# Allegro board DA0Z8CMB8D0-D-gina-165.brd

Outline 251.48 x 174.46 mm; copper layers: TOP, SGND, IN1, IN2, SVCC, IN3, SGND1, BOTTOM. Coordinates in mm from the lower left corner of the outline.

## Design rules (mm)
constraint set DEFAULT: min track width 0.14
net group DFP-S5(4: nets CRT_AUXN_C CRT_AUXP_C
net group DFP-S5(4.5: nets VMA_CLK0 VMA_CLK0#
net group W5(5.25)-T13B: nets VGA_COMP VGA_RST
net group W99-T123B: nets N103095748 TERM0
net group DFP-S4(4: nets M_A_DQS1 M_A_DQS2 M_A_DQS3 M_A_DQS5 M_A_DQS#1 M_A_DQS#2 M_A_DQS#3 M_A_DQS#5
net group DFP-S5(4: nets CRT_TXN0_C CRT_TXN1_C CRT_TXP0_C CRT_TXP1_C EDP_AUXN EDP_AUXP EDP_TXN0 EDP_TXN0_C EDP_TXN1 EDP_TXN1_C EDP_TXN2 EDP_TXN2_C EDP_TXN3 EDP_TXN3_C EDP_TXP0 EDP_TXP0_C EDP_TXP1 EDP_TXP1_C EDP_TXP2 EDP_TXP2_C EDP_TXP3 EDP_TXP3_C INT_HDMICLK+ INT_HDMICLK- INT_HDMITX0N INT_HDMITX0P PCIE_RXN3_C PCIE_RXP3_C PCIE_TX3+ PCIE_TX3- PCIE_TX4+ PCIE_TX4- PEG_RX0 PEG_RX#0 R_PEG_TX0 R_PEG_TX1 R_PEG_TX2 R_PEG_TX#0 R_PEG_TX#1 R_PEG_TX#2 USB3_TXN0 USB3_TXN0_C USB3_TXN1 USB3_TXN1_C USB3_TXP0 USB3_TXP0_C USB3_TXP1 USB3_TXP1_C USBP0+_C USBP0-_C USBP1+_R USBP1-_R USBP5+ USBP5+_R USBP5- USBP5-_R USBP6+ USBP6+_R USBP6- USBP6-_R WIGIG_TX3+ WIGIG_TX3-
net group DFP-S7(5.5: nets CK_XDP_N_R CK_XDP_P_R CLK_PCIE_WIGIGN CLK_PCIE_WIGIGP CLK_PCIE_XDPN CLK_PCIE_XDPP
net group DFP-S12(10: nets TX0N_R TX0P_R TX1N_R TX1P_R TX2N_R TX2P_R TX3N_R TX3P_R X-TX2N X-TX2P X-TX3N X-TX3P
net group W5(4.5: nets CRT_B1 CRT_BLU CRT_G1 CRT_GRE CRT_HPD CRT_R1 CRT_RED CRTHSYNC CRTVSYNC HSYNC ISPSCL ISPSDA VSYNC
net group W5-T13B: nets ACZ_SDIN0_R HDA_BCLK_R HDA_RST#_R HDA_SDO_R HDA_SYNC_R PCH_AZ_CODEC_BITCLK PCH_AZ_CODEC_RST# PCH_AZ_CODEC_SDIN0 PCH_AZ_CODEC_SDOUT PCH_AZ_CODEC_SYNC
net group W5.5(3.5)-T3B: nets SD_CLK
net group W5.5(4.5: nets M_B_DQ0 M_B_DQ1 M_B_DQ2 M_B_DQ3 M_B_DQ4 M_B_DQ5 M_B_DQ6 M_B_DQ7 M_B_DQ8 M_B_DQ9 M_B_DQ10 M_B_DQ11 M_B_DQ12 M_B_DQ13 M_B_DQ14 M_B_DQ15 M_B_DQ16 M_B_DQ17 M_B_DQ18 M_B_DQ19 M_B_DQ20 M_B_DQ21 M_B_DQ22 M_B_DQ23 M_B_DQ24 M_B_DQ25 M_B_DQ26 M_B_DQ27 M_B_DQ28 M_B_DQ29 M_B_DQ30 M_B_DQ31 M_B_DQ32 M_B_DQ33 M_B_DQ34 M_B_DQ35 M_B_DQ36 M_B_DQ37 M_B_DQ38 M_B_DQ39 M_B_DQ40 M_B_DQ41 M_B_DQ42 M_B_DQ43 M_B_DQ44 M_B_DQ45 M_B_DQ46 M_B_DQ47 M_B_DQ48 M_B_DQ49 M_B_DQ50 M_B_DQ51 M_B_DQ52 M_B_DQ53 M_B_DQ54 M_B_DQ55 M_B_DQ56 M_B_DQ57 M_B_DQ58 M_B_DQ59 M_B_DQ60 M_B_DQ61 M_B_DQ62 M_B_DQ63
net group W5.5(4.5: nets 27M_XTAL_IN_R 27M_XTAL_OUT A_LAD0_R A_LAD2_R A_LAD3_R CATERR# CLK_PCH_PCI3 CLK_PCH_PCI4 CLK_PCI_EC CLK_PCI_LPC CPU_DRAMRST# DDR_PG_CTRL H_PROCHOT# H_PROCHOT#_R HDMI_DDCCLK_COM HDMI_DDCCLK_MB HDMI_DDCCLK_SW HDMI_DDCDATA_COM HDMI_DDCDATA_MB HDMI_DDCDATA_SW LAN_XTAL2 LAN_XTALI LPC_LAD0 LPC_LAD1 LPC_LAD2 LPC_LAD3 LPC_LFRAME# PCH_SPI_CLK PCH_SPI_CLK_EC PCH_SPI_CS0# PCH_SPI_CS1# PCH_SPI_IO2 PCH_SPI_IO3 PCH_SPI_SI PCH_SPI_SI_EC PCH_SPI_SO PCH_SPI_SO_EC PCI_PLTRST# PCLK_TPM RTC_X1 RTC_X2 SD_CD# SD_CMD SD_DAT0 SD_DAT1 SD_DAT2 SD_DAT3 SD_WP SP5 SP6 SP7 SP8 SP9 SP10 SP12 SP13 SPI_CS0#_UR_ME SPI_HOLD_IO3_ME SPI_WP_IO2_ME VCCST_PWRGD VCCST_PWRGD_R XDP_BPM#0 XDP_BPM#1 XTAL24_IN XTAL24_OUT
net group W5.5(4.5: nets 2ND_MBCLK 2ND_MBDATA APWROK_R CL_CLK CL_DAT CL_RST# CLK_SCLK CLK_SDATA DNBSWON# DPWROK DPWROK_R DSWVREN EC_PWROK EC_PWROK_R MBCLK MBDATA PCH_INTVRMEN PCH_PWRBTN# PCH_RSMRST# RSMRST# RTC_RST# SIO_RCIN# SM_INTRUDER# SMB_ME0_CLK SMB_ME0_DAT SMB_ME1_CLK SMB_ME1_DAT SMB_PCH_CLK SMB_PCH_DAT SRTC_RST# SYS_PWROK SYS_PWROK_R SYS_RESET#
net group W5.5-T3B: nets H_CPU_SVIDART# H_CPU_SVIDCLK H_CPU_SVIDDAT VR_SVID_ALERT# VR_SVID_CLK VR_SVID_DATA
net group W5.5-T13B: nets H_PECI SATA_RCOMP THRMTRIP#
net group W7(5.5: nets FBA_CMD0 FBA_CMD1 FBA_CMD2 FBA_CMD3 FBA_CMD4 FBA_CMD5 FBA_CMD6 FBA_CMD7 FBA_CMD8 FBA_CMD9 FBA_CMD10 FBA_CMD11 FBA_CMD12 FBA_CMD13 FBA_CMD14 FBA_CMD15 FBA_CMD16 FBA_CMD17 FBA_CMD18 FBA_CMD19 FBA_CMD20 FBA_CMD21 FBA_CMD22 FBA_CMD23 FBA_CMD24 FBA_CMD25 FBA_CMD26 FBA_CMD27 FBA_CMD28 FBA_CMD29 FBA_CMD30 VMA_DM0 VMA_DM1 VMA_DM2 VMA_DM3 VMA_DM4 VMA_DM5 VMA_DM6 VMA_DM7 VMA_DQ0 VMA_DQ1 VMA_DQ2 VMA_DQ3 VMA_DQ4 VMA_DQ5 VMA_DQ6 VMA_DQ7 VMA_DQ8 VMA_DQ9 VMA_DQ10 VMA_DQ11 VMA_DQ12 VMA_DQ13 VMA_DQ14 VMA_DQ15 VMA_DQ16 VMA_DQ17 VMA_DQ18 VMA_DQ19 VMA_DQ20 VMA_DQ21 VMA_DQ22 VMA_DQ23 VMA_DQ24 VMA_DQ25 VMA_DQ26 VMA_DQ27 VMA_DQ28 VMA_DQ29 VMA_DQ30 VMA_DQ31 VMA_DQ32 VMA_DQ33 VMA_DQ34 VMA_DQ35 VMA_DQ36 VMA_DQ37 VMA_DQ38 VMA_DQ39 VMA_DQ40 VMA_DQ41 VMA_DQ42 VMA_DQ43 VMA_DQ44 VMA_DQ45 VMA_DQ46 VMA_DQ47 VMA_DQ48 VMA_DQ49 VMA_DQ50 VMA_DQ51 VMA_DQ52 VMA_DQ53 VMA_DQ54 VMA_DQ55 VMA_DQ56 VMA_DQ57 VMA_DQ58 VMA_DQ59 VMA_DQ60 VMA_DQ61 VMA_DQ62 VMA_DQ63
net group W8.5(7)-2B: nets M_B_A0 M_B_A1 M_B_A2 M_B_A3 M_B_A4 M_B_A5 M_B_A6 M_B_A7 M_B_A8 M_B_A9 M_B_A10 M_B_A11 M_B_A12 M_B_A13 M_B_A14 M_B_A15 M_B_BS#0 M_B_BS#1 M_B_BS#2 M_B_CAS# M_B_CKE0 M_B_CKE1 M_B_CS#0 M_B_CS#1 M_B_RAS# M_B_WE#
net group W8.5(7: nets M_A_DQ0 M_A_DQ1 M_A_DQ2 M_A_DQ3 M_A_DQ4 M_A_DQ5 M_A_DQ6 M_A_DQ7 M_A_DQ8 M_A_DQ9 M_A_DQ10 M_A_DQ11 M_A_DQ12 M_A_DQ13 M_A_DQ14 M_A_DQ15 M_A_DQ16 M_A_DQ17 M_A_DQ18 M_A_DQ19 M_A_DQ20 M_A_DQ21 M_A_DQ22 M_A_DQ23 M_A_DQ24 M_A_DQ25 M_A_DQ26 M_A_DQ27 M_A_DQ28 M_A_DQ29 M_A_DQ30 M_A_DQ31 M_A_DQ32 M_A_DQ33 M_A_DQ34 M_A_DQ35 M_A_DQ36 M_A_DQ37 M_A_DQ38 M_A_DQ39 M_A_DQ40 M_A_DQ41 M_A_DQ42 M_A_DQ43 M_A_DQ44 M_A_DQ45 M_A_DQ46 M_A_DQ47 M_A_DQ48 M_A_DQ49 M_A_DQ50 M_A_DQ51 M_A_DQ52 M_A_DQ53 M_A_DQ54 M_A_DQ55 M_A_DQ56 M_A_DQ57 M_A_DQ58 M_A_DQ59 M_A_DQ60 M_A_DQ61 M_A_DQ62 M_A_DQ63
net group W9.5(8: nets M_A_A0 M_A_A1 M_A_A2 M_A_A3 M_A_A4 M_A_A5 M_A_A6 M_A_A7 M_A_A8 M_A_A9 M_A_A10 M_A_A11 M_A_A12 M_A_A13 M_A_A14 M_A_A15 M_A_BS#0 M_A_BS#1 M_A_BS#2 M_A_CAS# M_A_CKE0 M_A_CKE1 M_A_CS#0 M_A_CS#1 M_A_RAS# M_A_WE#
net group W10-T13B: nets USBCOMP
net group W10-T123B: nets +PCH_VCCDSW +V1.05S_ASATA3PLL +V1.05S_AUSB3PLL +VCCRTCEXT BATLED0# BATLED1# FB_CAL_PU_GND FB_CAL_TERM_GND GPU_VCCP_SENSE GPU_VSSP_SENSE PWRLED# SUSLED# VDD33/18 VSS_SENSE VSS_SENSE_R
net group W12-T13B: nets SATA_IREF
net group W15-T13B: nets COMBO_MIC HP-L HP-L-1 HP-R HP-R-1 HPL_SYS HPR_SYS MIC2-L MIC2-R MIC2-VREFO MIC2_MIC SM_RCOMP_0 SM_RCOMP_1 SM_RCOMP_2
net group W15-T123B: nets +V1.5S_VCCATS +V3.3M_PSPI +V3.3S_VCCPTS FB_CAL_PD_VDDQ M_B_ODT0_DIMM M_B_ODT1_DIMM NV_PLLVDD PCH_VCC_1_1_21 PCIE_IREF PCIE_RCOMP SP_PLLVDD
net group W20-T123B: nets +1.05V_GFX +1.5VAVDD2 +3V_EC +3V_GFX +3V_RTC +3V_WLAN +3VCC_S5 +3VDVDD +3VPCU_EC +3VPCU_ECPLL +5V_FAN1 +5V_FAN2 +5V_HDD +5V_KB +5V_KB_R +5VA +5VMCU +5VPVDD1 +5VPVDD2 +A3VPCU +DDR_VTT_RUN +FB_PLLAVDD +SMDDR_VREF_DIMM +SMDDR_VREF_DQ0 +SMDDR_VREF_DQ1 +TPVDD +V1.05DX_MODPHY +V1.05M_VCCASW +V1.05S_AIDLE +V1.05S_APLLOPI +V1.05S_AXCK_DCB +V1.05S_AXCK_LCPLL +V1.05S_CORE_PCH +V1.05S_VCCUSBCORE +V3.3DX_1.5DX_1.8DX_AUDIO +V3.3S_VCCPCORE +VCCIO_OUT +VCCPDSW +VREF_CA_CPU +VREFDQ_SA_M3 +VREFDQ_SB_M3 +WL_VDD CARD_3V3 CCD_PWR CFG_RCOMP DAC_VDDC ECAGND EDP_RCOMP EVDD10 HDMI_5V IVDDO IVDDO_18 LCD_VIN LCDVCC LCDVCC_1 N100631544 N107600611 N107600701 OPI_COMP1 PEX_PLLVDD RX_DVDD18 TD_IREF TP_PWR USBPWR1 USBPWR2 USBPWR3 USBPWR4 VDD10 VDD33 VDDREG VREFC_VMA1 VREFC_VMA3 VREFD_VMA1 VREFD_VMA3
net group W50-T123B: nets MCT1 MCT2 MCT3 MCT4

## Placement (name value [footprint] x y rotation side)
C1  *0.1u/10v_4  [CC0402]  33.49 170.04 90 top
C2  *0.1u/10v_4  [CC0402]  34.63 170.04 90 top
C3  *0.1u/10v_4  [CC0402]  35.77 170.04 90 top
C4  *0.1u/10v_4  [CC0402]  59.27 170.04 90 top
C5  *0.1u/10v_4  [CC0402]  60.41 170.04 90 top
C6  *0.1u/10v_4  [CC0402]  61.55 170.04 90 top
C7  *6.8p/50v_4  [CC0402]  147.79 166.99 180 top
C8  0.01u/16v_4  [CC0402]  144.74 165.97 90 top
C9  *6.8p/50v_4  [CC0402]  147.79 165.59 180 top
C10  ev@0.1u/10v_4  [CC0402]  59.01 165.08 0 top
C11  ev@0.1u/10v_4  [CC0402]  61.17 165.08 0 top
C12  ev@0.1u/10v_4  [CC0402]  38.87 164.43 90 top
C13  ev@1u/6.3v_4  [CC0402]  39.89 164.43 90 top
C14  0.1u/10v_4  [CC0402]  99.78 163.94 180 top
C15  ev@10u/6.3v_6  [CC0603]  32.22 163.81 270 top
C16  ev@4.7u/6.3v_6  [CC0603]  33.49 163.81 270 top
C17  ev@0.1u/10v_4  [CC0402]  34.68 163.8 270 top
C18  ev@1u/6.3v_4  [CC0402]  35.7 163.8 90 top
C19  *ev@120p/50v_4  [CC0402]  36.71 163.8 270 top
C20  ev@1u/6.3v_4  [CC0402]  37.73 163.8 90 top
C21  ev@10u/6.3v_6  [CC0603]  30.31 162.54 0 top
C22  ev@10u/6.3v_6  [CC0603]  57.54 162.14 270 top
C23  ev@0.1u/10v_4  [CC0402]  51.83 162.02 270 top
C24  *ev@120p/50v_4  [CC0402]  52.97 162.02 270 top
C25  ev@0.1u/10v_4  [CC0402]  54.11 162.02 270 top
C26  ev@0.1u/10v_4  [CC0402]  55.25 162.02 270 top
C27  ev@1u/6.3v_4  [CC0402]  56.4 162.02 90 top
C28  5.6p/16v_4  [CC0402]  103.84 161.65 0 top
C29  5.6p/16v_4  [CC0402]  105.88 161.65 0 top
C30  5.6p/16v_4  [CC0402]  107.91 161.65 0 top
C31  0.1u/10v_4  [CC0402]  110.96 161.65 180 top
C32  ev@0.1u/10v_4  [CC0402]  31 161.26 180 top
C33  10p/50v_4  [CC0402]  109.43 161.15 270 top
C34  10p/50v_4  [CC0402]  112.61 161.15 270 top
C35  *10p/50v_4  [CC0402]  113.62 161.15 270 top
C36  *0.22u/6.3v_4  [CC0402]  110.96 160.64 180 top
C37  ev@0.1u/10v_4  [CC0402]  31 160.11 0 top
C38  5.6p/16v_4  [CC0402]  103.84 159.62 180 top
C39  5.6p/16v_4  [CC0402]  105.88 159.62 180 top
C40  5.6p/16v_4  [CC0402]  107.91 159.62 180 top
C41  0.1u/10v_4  [CC0402]  102.07 159.24 270 top
C42  *ev@120p/50v_4  [CC0402]  57.29 158.84 180 top
C43  *1000p/50v_4  [CC0402]  82.51 158.35 90 top
C44  *1000p/50v_4  [CC0402]  83.65 158.35 90 top
C45  ev@0.1u/10v_4  [CC0402]  57.29 157.83 180 top
C46  ev@1u/6.3v_4  [CC0402]  56.65 156.3 270 top
C47  *0.1u/10v_4  [CC0402]  123.91 155.69 90 top
C48  ev@0.01u/25v_4  [CC0402]  31 155.54 180 top
C49  *6.8p/50v_4  [CC0402]  153.37 155.43 270 top
C50  *6.8p/50v_4  [CC0402]  154.77 155.43 270 top
C51  0.1u/10v_4  [CC0402]  126.2 155.3 0 top
C52  0.1u/10v_4  [CC0402]  104.86 155.18 270 top
C53  0.1u/10v_4  [CC0402]  105.88 155.18 270 top
C54  0.1u/10v_4  [CC0402]  106.89 155.18 270 top
C55  ev@4.7u/6.3v_6  [CC0603]  72.73 154.67 90 top
C56  ev@1u/6.3v_4  [CC0402]  71.21 154.54 270 top
C57  *0.1u/10v_4  [CC0402]  23.45 153.02 270 top
C58  *0.1u/10v_4  [CC0402]  91.02 151.37 90 top
C59  22u/6.3v_8  [CC0805]  126.58 150.99 90 top
C60  22u/6.3v_8  [CC0805]  128.61 150.99 90 top
C61  0.1u/10v_4  [CC0402]  106.89 150.86 0 top
C62  *1000p/50v_4  [CC0402]  130.13 150.73 90 top
C63  *ev@1000p/50v_4  [CC0402]  19.82 150.71 0 top
C64  ev@1u/6.3v_4  [CC0402]  70.19 149.88 90 top
C65  ev@1u/6.3v_4  [CC0402]  71.46 149.88 90 top
C66  ev@0.1u/10v_4  [CC0402]  72.73 149.88 90 top
C67  ev@0.1u/10v_4  [CC0402]  74 149.88 90 top
C68  ev@1u/6.3v_4  [CC0402]  68.97 149.83 90 top
C69  ev@0.1u/10v_4  [CC0402]  75.19 149.83 90 top
C70  ev@1000p/50v_4  [CC0402]  17.23 149.72 270 top
C71  0.1u/10v_4  [CC0402]  103.34 149.34 270 top
C72  0.1u/10v_4  [CC0402]  106.13 149.34 270 top
C73  ev@4.7u/6.3v_6  [CC0603]  77.23 149.32 180 top
C74  *0.1u/10v_4  [CC0402]  89.11 148.57 0 top
C75  1u/6.3v_4  [CC0402]  107.78 148.32 90 top
C76  ev@0.1u/10v_4  [CC0402]  69.61 148.12 0 top
C77  ev@1000p/50v_4  [CC0402]  23.45 148.07 90 top
C78  ev@10u/6.3v_6  [CC0603]  76.46 147.54 180 top
C79  ev@1u/6.3v_4  [CC0402]  74.56 147.16 90 top
C80  10u/6.3v_6  [CC0603]  108.8 146.54 180 top
C81  ev@0.1u/10v_4  [CC0402]  76.46 146.27 0 top
C82  *0.1u/10v_4  [CC0402]  130.16 145.65 0 top
C83  ev@1u/6.3v_4  [CC0402]  76.46 145.13 0 top
C84  ev@4.7u/6.3v_6  [CC0603]  28.53 144.89 90 top
C85  *ev@1000p/50v_4  [CC0402]  16.72 144 180 top
C86  ev@1u/6.3v_4  [CC0402]  76.46 143.98 0 top
C87  47u/6.3v_8  [CC0805]  145.37 143.11 0 top
C88  ev@10u/6.3v_6  [CC0603]  76.72 142.71 180 top
C89  ev@4.7u/6.3v_6  [CC0603]  34.38 142.35 90 top
C90  *22u/6.3v_8  [CC0805]  134.73 141.97 0 top
C91  *ev@10u/6.3vs_6  [CC0603]  36.28 141.46 0 top
C92  ev@4.7u/6.3v_6  [CC0603]  76.72 141.32 180 top
C93  22u/6.3v_8  [CC0805]  127.72 141.21 270 top
C94  *22u/6.3v_8  [CC0805]  129.75 141.21 90 top
C95  22u/6.3v_8  [CC0805]  132.01 141.21 270 top
C96  47u/6.3v_8  [CC0805]  145.4 141.08 0 top
C97  ev@22u/6.3vs_6  [CC0603]  36.28 140.19 180 top
C98  ev@1u/6.3v_4  [CC0402]  76.34 140.05 0 top
C99  47u/6.3v_8  [CC0805]  134.73 139.94 180 top
C100  47u/6.3v_8  [CC0805]  141.82 139.51 180 top
C101  ev@0.1u/10v_4  [CC0402]  76.34 138.9 0 top
C102  *1000p/50v_4  [CC0402]  26.88 137.65 90 top
C103  47u/6.3v_8  [CC0805]  133.05 137.6 180 top
C104  47u/6.3v_8  [CC0805]  141.82 137.5 180 top
C105  ev@22u/6.3vs_6  [CC0603]  31.84 137.14 0 top
C106  ev@10u/6.3vs_6  [CC0603]  36.03 136.89 270 top
C107  ev@0.1u/10v_4  [CC0402]  77.94 136.64 90 top
C108  ev@4.7u/6.3v_6  [CC0603]  39.63 136.24 180 top
C109  ev@0.1u/10v_4  [CC0402]  47.63 135.98 270 top
C110  ev@0.1u/10v_4  [CC0402]  48.65 135.98 270 top
C111  ev@10u/6.3vs_6  [CC0603]  31.84 135.87 180 top
C112  ev@4.7u/6.3v_6  [CC0603]  45.22 135.73 270 top
C113  ev@1u/10v_6  [CC0603]  46.49 135.73 270 top
C114  ev@4.7u/6.3v_6  [CC0603]  37.32 135.63 270 top
C115  ev@22u/6.3vs_6  [CC0603]  28.28 135.49 90 top
C116  ev@0.1u/10v_4  [CC0402]  41.95 135.27 90 top
C117  ev@10u/6.3v_6  [RC0603]  39.63 135.07 0 top
C118  *ev@22u/6.3vs_6  [CC0603]  31.84 134.6 0 top
C119  ev@22u/6.3v_8  [CC0805]  43.52 134.33 270 top
C120  ev@0.1u/10v_4  [CC0402]  77.1 134.2 90 top
C121  ev@0.1u/10v_4  [CC0402]  78.24 134.2 90 top
C122  ev@0.1u/10v_4  [CC0402]  48.17 134.08 180 top
C123  ev@1u/6.3v_4  [CC0402]  37.6 133.7 180 top
C124  ev@4.7u/6.3v_6  [CC0603]  40.65 133.44 180 top
C125  ev@4.7u/6.3v_6  [CC0603]  45.86 133.44 0 top
C126  ev@10u/6.3vs_6  [CC0603]  31.84 133.33 180 top
C127  100u/6.3v_1206  [CC1206]  241.89 133.21 90 top
C128  ev@0.22u/10v_4  [CC0402]  28.39 133.06 180 top
C129  ev@0.1u/10v_4  [CC0402]  48.17 133.06 180 top
C130  ev@0.1u/10v_4  [CC0402]  76.72 132.17 0 top
C131  ev@22u/6.3vs_6  [CC0603]  31.84 132.06 0 top
C132  ev@0.22u/10v_4  [CC0402]  28.39 132.05 180 top
C133  ev@1u/6.3v_4  [CC0402]  35.39 131.94 180 top
C134  ev@0.1u/10v_4  [CC0402]  37.45 131.92 180 top
C135  ev@4.7u/6.3v_6  [CC0603]  39.76 131.54 180 top
C136  ev@4.7u/6.3v_6  [CC0603]  47.1 131.23 90 top
C137  ev@1u/10v_6  [CC0603]  48.52 131.16 270 top
C138  ev@0.22u/10v_4  [CC0402]  28.39 130.9 180 top
C139  ev@10u/6.3v_6  [CC0603]  76.54 130.88 180 top
C140  ev@4.7u/6.3v_6  [CC0603]  42.27 130.77 90 top
C141  ev@1u/6.3v_4  [CC0402]  35.39 130.41 180 top
C142  ev@4.7u/6.3v_6  [CC0603]  39.79 130.29 180 top
C143  ev@1u/6.3v_4  [CC0402]  37.47 130.27 0 top
C144  ev@0.22u/10v_4  [CC0402]  28.39 129.89 180 top
C145  ev@0.1u/10v_4  [CC0402]  76.21 129.63 0 top
C146  ev@330u_2.5v_3528  [CC3528]  44.69 129.2 90 top
C147  ev@0.22u/10v_4  [CC0402]  28.39 128.74 180 top
C148  ev@0.1u/10v_4  [CC0402]  48.52 128.74 270 top
C149  ev@4.7u/6.3v_6  [CC0603]  47.1 128.64 270 top
C150  *ev@1u/6.3v_4  [CC0402]  37.6 128.62 90 top
C151  ev@4.7u/6.3v_6  [CC0603]  39.76 128.49 180 top
C152  ev@1u/6.3v_4  [CC0402]  76.21 128.49 0 top
C153  ev@0.22u/10v_4  [CC0402]  28.39 127.73 180 top
C154  ev@4.7u/6.3v_6  [CC0603]  42.27 127.64 270 top
C155  ev@4.7u/6.3v_6  [CC0603]  74.76 127.19 180 top
C156  *0.1u/10v_4  [CC0402]  82.76 127.11 0 top
C157  0.1u/10v_4  [CC0402]  155.66 126.73 90 top
C158  ev@0.22u/10v_4  [CC0402]  28.39 126.58 180 top
C159  ev@4.7u/6.3v_6  [CC0603]  39.76 126.46 180 top
C160  *ev@1u/6.3v_4  [CC0402]  37.6 126.33 90 top
C161  ev@0.1u/10v_4  [CC0402]  47.46 126.32 90 top
C162  ev@10u/6.3v_6  [CC0603]  74.76 125.8 180 top
C163  1000p/50v_4  [CC0402]  243.67 125.71 180 top
C164  ev@0.22u/10v_4  [CC0402]  28.39 125.57 180 top
C165  1u/6.3v_4  [CC0402]  132.42 125.33 0 top
C166  ev@0.1u/10v_4  [CC0402]  42.55 125.29 90 top
C167  ev@0.1u/10v_4  [CC0402]  43.7 125.29 90 top
C168  ev@1u/6.3v_4  [CC0402]  40.9 124.93 180 top
C169  ev@1u/6.3v_4  [CC0402]  45.35 124.81 0 top
C170  ev@0.1u/10v_4  [CC0402]  38.06 124.75 0 top
C171  ev@0.1u/10v_4  [CC0402]  47.58 124.7 0 top
C172  ev@0.1u/10v_4  [CC0402]  74.51 124.53 0 top
C173  1u/6.3v_4  [CC0402]  137.5 124.44 180 top
C174  10u/6.3v_6  [CC0603]  129.88 124.32 180 top
C175  1u/6.3v_4  [CC0402]  132.42 124.32 180 top
C176  22u/6.3v_8  [CC0805]  159.17 124.19 90 top
C177  22u/6.3v_8  [CC0805]  112.35 124.06 0 top
C178  1u/6.3v_4  [CC0402]  134.58 123.94 0 top
C179  22u/6.3v_8  [CC0805]  115.08 123.93 270 top
C180  *22u/6.3v_8  [CC0805]  117.11 123.93 90 top
C181  22u/6.3v_8  [CC0805]  119.15 123.93 270 top
C182  22u/6.3v_8  [CC0805]  121.18 123.93 90 top
C183  22u/6.3v_8  [CC0805]  123.21 123.93 270 top
C184  22u/6.3v_8  [CC0805]  125.24 123.93 90 top
C185  22u/6.3v_8  [CC0805]  127.27 123.93 90 top
C186  ev@1u/6.3v_4  [CC0402]  46.19 123.68 180 top
C187  ev@4.7u/6.3v_6  [CC0603]  35.39 123.58 0 top
C188  ev@4.7u/6.3v_6  [CC0603]  38.06 123.58 180 top
C189  ev@0.1u/10v_4  [CC0402]  74.51 123.51 0 top
C190  *ev@0.1u/10v_4  [CC0402]  28.33 123.28 0 top
C191  1u/6.3v_4  [CC0402]  139.2 123.2 270 top
C192  0.1u/10v_4  [CC0402]  89.42 123.17 180 top
C193  *22p/50v_4  [CC0402]  154.26 123.05 180 top
C194  *1u/6.3v_4  [CC0402]  137.12 122.79 270 top
C195  ev@1u/10v_6  [CC0603]  51.9 122.67 180 top
C196  ev@1u/10v_6  [CC0603]  47.2 122.54 0 top
C197  ev@0.1u/10v_4  [CC0402]  59.45 122.52 270 top
C198  ev@1u/6.3v_4  [CC0402]  60.46 122.52 270 top
C199  ev@0.1u/10v_4  [CC0402]  61.6 122.52 90 top
C200  ev@0.01u/25v_4  [CC0402]  66.56 122.52 270 top
C201  ev@0.1u/10v_4  [CC0402]  68.84 122.52 90 top
C202  *ev@120p/50v_4  [CC0402]  70.11 122.52 90 top
C203  ev@0.1u/10v_4  [CC0402]  71.38 122.52 90 top
C204  ev@1u/6.3v_4  [CC0402]  72.65 122.52 270 top
C205  1u/6.3v_4  [CC0402]  135.54 122.44 0 top
C206  ev@4.7u/6.3vs_6  [CC0603]  39.33 122.41 180 top
C207  ev@4.7u/6.3v_6  [CC0603]  62.87 122.39 90 top
C208  ev@1u/6.3v_4  [CC0402]  74.56 122.27 0 top
C209  1u/6.3v_4  [CC0402]  8.09 122.03 270 top
C210  22u/6.3v_8  [CC0805]  112.35 122.03 0 top
C211  10u/6.3v_6  [CC0603]  129.75 121.78 180 top
C212  1u/6.3v_4  [CC0402]  138.77 121.52 0 top
C213  ev@4.7u/6.3v_6  [CC0603]  51.9 121.4 180 top
C214  ev@4.7u/6.3v_6  [CC0603]  47.2 121.27 0 top
C215  ev@4.7u/6.3vs_6  [CC0603]  39.33 121.14 180 top
C216  1u/6.3v_4  [CC0402]  138.77 120.51 0 top
C217  ev@4.7u/6.3vs_6  [CC0603]  39.33 119.87 180 top
C218  ev@22u/6.3vs_6  [CC0603]  43.27 119.74 180 top
C219  22u/6.3v_8  [CC0805]  115.55 119.74 270 top
C220  22u/6.3v_8  [CC0805]  117.69 119.74 270 top
C221  22u/6.3v_8  [CC0805]  119.72 119.74 90 top
C222  22u/6.3v_8  [CC0805]  121.75 119.74 270 top
C223  22u/6.3v_8  [CC0805]  123.78 119.74 90 top
C224  22u/6.3v_8  [CC0805]  125.79 119.74 270 top
C225  0.1u/10v_4  [CC0402]  138.64 119.49 180 top
C226  *0.1u/10v_4  [CC0402]  7.2 119.24 90 top
C227  1u/6.3v_4  [CC0402]  127.85 119.24 90 top
C228  22u/6.3v_8  [CC0805]  112.61 119.11 0 top
C229  1u/6.3v_4  [CC0402]  136.61 118.91 0 top
C230  ev@4.7u/6.3v_6  [CC0603]  43.27 118.47 180 top
C231  1u/6.3v_4  [CC0402]  138.64 118.47 0 top
C232  ev@47u/6.3v_8  [CC0805]  38.95 118.22 180 top
C233  0.1u/10v_4  [CC0402]  148.85 117.71 90 top
C234  ev@22u/6.3vs_6  [CC0603]  46.36 117.69 0 top
C235  22u/6.3v_8  [CC0805]  153.5 117.59 180 top
C236  1u/6.3v_4  [CC0402]  132.04 117.46 90 top
C237  ev@0.1u/10v_4  [CC0402]  43.01 117.33 180 top
C238  1u/6.3v_4  [CC0402]  136.36 117.33 0 top
C239  1u/6.3v_4  [CC0402]  138.52 117.33 0 top
C240  0.47u/25v_6  [CC0603]  133.5 116.85 90 top
C241  *4.7u/6.3v_6  [CC0603]  129.75 116.82 180 top
C242  2.2u/6.3v_6  [CC0603]  120.99 116.7 90 top
C243  10u/6.3v_6  [CC0603]  122.41 116.7 270 top
C244  10u/6.3v_6  [CC0603]  123.66 116.7 270 top
C245  2.2u/6.3v_6  [CC0603]  124.93 116.7 90 top
C246  22u/6.3v_8  [CC0805]  111.46 116.27 270 top
C247  ev@22u/6.3v_8  [CC0805]  38.95 116.19 180 top
C248  ev@4.7u/6.3vs_6  [CC0603]  42 116.06 0 top
C249  0.1u/10v_4  [CC0402]  138.39 115.93 180 top
C250  1u/6.3v_4  [CC0402]  132.04 115.43 90 top
C251  0.1u/10v_4  [CC0402]  135.31 115.43 90 top
C252  1u/6.3v_4  [CC0402]  136.36 115.43 270 top
C253  1u/6.3v_4  [CC0402]  133.69 115.05 0 top
C254  1u/6.3v_4  [CC0402]  130.26 114.92 180 top
C255  1u/6.3v_4  [CC0402]  138.64 114.92 0 top
C256  0.1u/10v_4  [CC0402]  12.79 114.79 0 top
C257  ev@4.7u/6.3vs_6  [CC0603]  42 114.79 0 top
C258  4.7u/25v_8  [CC0805]  52.28 109.46 270 top
C259  1000p/50v_4  [CC0402]  50.5 109.33 90 top
C260  *47u/6.3v_8  [CC0805]  156.93 108.77 270 top
C261  1000p/50v_4  [CC0402]  54.44 107.55 90 top
C262  *10p/50v_4  [CC0402]  55.71 107.55 270 top
C263  1u/6.3v_4  [CC0402]  242.4 110.09 270 top
C264  *0.1u/10v_4  [CC0402]  156.42 106.54 0 top
C265  *1000p/50v_4  [CC0402]  156.42 105.52 0 top
C266  0.1u/10v_4  [CC0402]  160.74 105.39 270 top
C267  ev@0.1u/10v_4  [CC0402]  37.3 104.5 180 top
C268  2.2u/6.3v_6  [CC0603]  118.07 104.43 0 top
C269  10u/6.3v_6  [CC0603]  121.24 104 180 top
C270  10u/6.3v_6  [CC0603]  123.35 103.72 90 top
C271  10u/6.3v_6  [CC0603]  115.78 103.62 90 top
C272  10u/6.3v_6  [CC0603]  125.05 103.62 90 top
C273  *1000p/50v_4  [CC0402]  159.09 102.98 180 top
C274  *tpl@10p/50v_4  [CC0402]  56.15 102.84 180 top
C275  ev@0.1u/10v_4  [CC0402]  41.61 102.73 270 top
C276  2.2u/6.3v_6  [CC0603]  113.75 102.13 180 top
C277  *tpl@1000p/50v_4  [CC0402]  56.15 101.83 0 top
C278  *5.6p/16v_4  [CC0402]  58 100.82 270 top
C279  *5.6p/16v_4  [CC0402]  59.01 100.82 270 top
C280  *5.6p/16v_4  [CC0402]  60.03 100.82 270 top
C281  *5.6p/16v_4  [CC0402]  61.05 100.82 270 top
C282  *5.6p/16v_4  [CC0402]  62.06 100.82 270 top
C283  *5.6p/16v_4  [CC0402]  63.08 100.82 270 top
C284  *5.6p/16v_4  [CC0402]  64.09 100.82 270 top
C285  *5.6p/16v_4  [CC0402]  65.11 100.82 270 top
C286  22u/6.3v_8  [CC0805]  51.65 100.69 180 top
C287  *0.1u/10v_4  [CC0402]  45.42 100.57 270 top
C288  *18p/50v_4  [CC0402]  140.42 99.93 270 top
C289  *18p/50v_4  [CC0402]  141.44 99.93 270 top
C290  *18p/50v_4  [CC0402]  142.71 99.93 270 top
C291  *470u/2v_7343  [CC7343]  124.04 99.04 0 top
C292  22u/6.3v_8  [CC0805]  141.94 95.36 180 top
C293  4.7u/6.3v_6  [CC0603]  219.8 93.58 90 top
C294  0.1u/10v_4  [CC0402]  213.06 93.33 90 top
C295  0.1u/10v_4  [CC0402]  214.08 93.33 90 top
C296  0.1u/10v_4  [CC0402]  215.6 93.33 90 top
C297  0.1u/10v_4  [CC0402]  217.51 93.33 90 top
C298  0.1u/10v_4  [CC0402]  218.65 93.33 90 top
C299  0.1u/10v_4  [CC0402]  105.5 93.07 270 top
C300  0.1u/10v_4  [CC0402]  210.52 92.44 90 top
C301  12p/50_4  [CC0402]  224.49 92.44 0 top
C302  12p/50_4  [CC0402]  226.65 92.44 180 top
C303  0.1u/10v_4  [CC0402]  221.95 89.52 90 top
C304  0.022u/16v_4  [CC0402]  94.76 89.26 0 top
C305  0.1u/10v_4  [CC0402]  230.34 89.01 180 top
C306  330u/2v_7343  [CC7343]  116.04 88.12 0 top
C307  *0.33u/10v_6  [CC0603]  149.56 88.12 90 top
C308  0.1u/10v_4  [CC0402]  230.34 87.99 180 top
C309  0.1u/10v_4  [CC0402]  223.48 86.6 0 top
C310  2.2u/6.3v_6  [CC0603]  94.89 85.76 0 top
C311  0.1u/10v_4  [CC0402]  223.48 85.58 0 top
C312  4.7u/6.3v_6  [CC0603]  161.82 84.61 0 top
C313  2.2u/6.3v_6  [CC0603]  157.69 84.44 0 top
C314  0.1u/10v_4  [CC0402]  223.48 84.18 0 top
C315  0.1u/10v_4  [CC0402]  124.55 83.8 90 top
C316  10u/6.3v_6  [CC0603]  127.21 83.8 270 top
C317  0.1u/10v_4  [CC0402]  135.47 83.8 90 top
C318  10u/6.3v_6  [CC0603]  120.99 83.68 270 top
C319  *10u/6.3v_6  [CC0603]  129.63 83.68 270 top
C320  10u/6.3v_6  [CC0603]  132.44 83.68 270 top
C321  470p/50v_4  [CC0402]  94.89 83.54 180 top
C322  4.7u/6.3v_6  [CC0603]  161.82 83.41 0 top
C323  0.1u/10v_4  [CC0402]  207.48 82.91 270 top
C324  1u/6.3v_4  [CC0402]  208.49 82.91 90 top
C325  *4.7u/6.3v_6  [CC0603]  225.26 82.91 270 top
C326  *0.1u/10v_4  [CC0402]  32.72 82.53 270 top
C327  0.1u/10v_4  [CC0402]  94.83 82.28 0 top
C328  1u/6.3v_4  [CC0402]  161.76 82.28 180 top
C329  0.1u/10v_4  [CC0402]  223.48 81.9 0 top
C330  0.1u/10v_4  [CC0402]  207.98 81.39 0 top
C331  1u/6.3v_4  [CC0402]  161.76 81.26 180 top
C332  0.1u/10v_4  [CC0402]  207.98 80.37 0 top
C333  4.7u/6.3v_6  [CC0603]  208.11 79.1 180 top
C334  0.1u/10v_4  [CC0402]  210.27 78.72 270 top
C335  0.1u/10v_4  [CC0402]  215.6 78.6 270 top
C336  0.1u/10v_4  [CC0402]  219.29 78.34 180 top
C337  10u/6.3v_6  [CC0603]  161.88 78.09 0 top
C338  *0.1u/10v_4  [CC0402]  33.11 77.96 0 top
C339  2.2u/6.3v_6  [CC0603]  137.63 77.2 270 top
C340  *100u/6.3v_3528  [CC3528]  36.53 77.07 270 top
C341  4.7u/6.3v_6  [CC0603]  219.54 77.07 180 top
C342  0.1u/10v_4  [CC0402]  223.48 77.07 180 top
C343  1u/6.3v_4  [CC0402]  161.82 76.94 180 top
C344  10u/6.3v_6  [CC0603]  32.96 76.83 0 top
C345  0.1u/10v_4  [CC0402]  157.95 76.06 0 top
C346  10u/6.3v_6  [CC0603]  135.85 75.93 90 top
C347  *1u/6.3v_4  [CC0402]  78.67 76.01 90 top
C348  10u/6.3v_6  [CC0603]  122.13 75.8 90 top
C349  10u/6.3v_6  [CC0603]  127.62 75.8 90 top
C350  *10u/6.3v_6  [CC0603]  131.4 75.8 90 top
C351  0.1u/10v_4  [CC0402]  133.31 75.8 270 top
C352  4.7u/6.3v_6  [CC0603]  223.48 75.8 180 top
C353  1u/6.3v_4  [CC0402]  161.82 75.79 180 top
C354  0.01u/16v_4  [CC0402]  33.07 75.74 0 top
C355  0.1u/10v_4  [CC0402]  123.66 75.68 270 top
C356  0.1u/10v_4  [CC0402]  126.32 75.68 270 top
C357  0.1u/10v_4  [CC0402]  139.28 75.68 180 top
C358  *0.1u/10v_4  [CC0402]  33.07 74.73 0 top
C359  *1000p/50v_4  [CC0402]  138.9 74.66 0 top
C360  4.7u/6.3v_6  [CC0603]  161.69 74.52 0 top
C361  0.01u/16v_4  [CC0402]  33.07 73.71 0 top
C362  *0.1u/10v_4  [CC0402]  104.99 73.39 0 top
C363  *10u/6.3v_6  [CC0603]  122.91 73.24 0 top
C364  *1u/6.3v_4  [CC0402]  90.13 73.14 180 top
C365  1u/6.3v_4  [CC0402]  65.11 72.63 90 top
C366  1u/6.3v_4  [CC0402]  96.54 71.73 0 top
C367  10u/6.3v_6  [CC0603]  93.24 71.6 0 top
C368  0.022u/16v_4  [CC0402]  63.9 71.35 90 top
C369  0.1u/10v_4  [CC0402]  141.82 71.23 270 top
C370  0.1u/10v_4  [CC0402]  230.34 71.1 180 top
C371  0.1u/10v_4  [CC0402]  145.37 70.98 270 top
C372  0.1u/10v_4  [CC0402]  148.29 70.98 270 top
C373  *0.1u/10v_4  [CC0402]  96.54 70.46 0 top
C374  10u/6.3v_6  [CC0603]  65.01 70.21 270 top
C375  *0.1u/10v_4  [CC0402]  124.93 70.21 180 top
C376  *1u/6.3v_4  [CC0402]  92.98 70.21 180 top
C377  0.1u/10v_4  [CC0402]  230.34 70.09 180 top
C378  0.1u/10v_4  [CC0402]  222.46 69.83 0 top
C379  *1u/6.3v_4  [CC0402]  96.54 69.32 0 top
C380  1u/6.3v_4  [CC0402]  92.98 68.81 180 top
C381  *1000p/50v_4  [CC0402]  165.82 68.56 90 top
C382  *0.1u/10v_4  [CC0402]  127.52 69.07 180 top
C383  *1u/6.3v_4  [CC0402]  96.54 68.17 0 top
C384  1u/6.3v_4  [CC0402]  124.93 67.93 180 top
C385  *1u/6.3v_4  [CC0402]  65.11 67.55 90 top
C386  *1u/6.3v_4  [CC0402]  92.98 67.41 180 top
C387  *0.1u/10v_4  [CC0402]  130.51 67.17 180 top
C388  *1u/6.3v_4  [CC0402]  96.54 67.03 0 top
C389  1u/6.3v_4  [CC0402]  124.93 66.91 180 top
C390  470p/50v_4  [CC0402]  63.33 66.53 180 top
C391  *0.1u/10v_4  [CC0402]  165.82 66.53 270 top
C392  *1u/6.3v_4  [CC0402]  92.98 66.01 180 top
C393  *0.1u/10v_4  [CC0402]  124.93 65.9 180 top
C394  1u/6.3v_4  [CC0402]  61.68 65.77 270 top
C395  1u/6.3v_4  [CC0402]  96.54 65.63 0 top
C396  1u/6.3v_4  [CC0402]  65.11 65.26 90 top
C397  0.1u/10v_4  [CC0402]  136.86 65.13 0 top
C398  *0.1u/10v_4  [CC0402]  124.93 64.88 180 top
C399  0.1u/10v_4  [CC0402]  158.84 64.88 180 top
C400  *0.1u/10v_4  [CC0402]  226.4 64.25 0 top
C401  0.047u/25v_4  [CC0402]  124.93 63.86 180 top
C402  0.1u/10v_4  [CC0402]  158.84 63.86 180 top
C403  0.047u/25v_4  [CC0402]  93.49 63.75 90 top
C404  0.047u/25v_4  [CC0402]  95.91 63.73 90 top
C405  1u/6.3v_4  [CC0402]  214.59 63.61 0 top
C406  0.047u/25v_4  [CC0402]  62.44 63.48 0 top
C407  0.1u/10v_4  [CC0402]  136.86 62.47 0 top
C408  0.047u/25v_4  [CC0402]  96.86 61.2 90 top
C409  *10p/50v_4  [CC0402]  134.58 61.2 180 top
C410  0.1u/10v_4  [CC0402]  136.86 61.2 0 top
C411  0.047u/25v_4  [CC0402]  92.41 60.56 90 top
C412  0.047u/25v_4  [CC0402]  125.1 59.83 0 top
C413  *0.1u/10v_4  [CC0402]  96.41 59.54 0 top
C414  1u/6.3v_4  [CC0402]  60.41 59.04 270 top
C415  *0.1u/10v_4  [CC0402]  125.1 58.66 180 top
C416  1u/6.3v_4  [CC0402]  137.37 58.66 90 top
C417  *0.1u/10v_4  [CC0402]  92.92 58.53 180 top
C418  *10u/6.3v_6  [CC0603]  96.16 58.39 180 top
C419  0.022u/16v_4  [CC0402]  56.22 58.15 90 top
C420  1u/6.3v_4  [CC0402]  92.92 57.51 180 top
C421  1u/6.3v_4  [CC0402]  125.1 57.49 180 top
C422  1u/6.3v_4  [CC0402]  96.41 57.12 0 top
C423  1u/6.3v_4  [CC0402]  60.41 56.75 270 top
C424  *0.1u/10v_4  [CC0402]  92.98 56.24 180 top
C425  10u/6.3v_6  [CC0603]  125.37 56.24 0 top
C426  *10u/6.3v_6  [CC0603]  240.62 55.74 90 top
C427  *0.1u/10v_4  [CC0402]  241.89 55.48 270 top
C428  *0.1u/10v_4  [CC0402]  96.41 55.47 0 top
C429  0.1u/10v_4  [CC0402]  136.99 55.23 0 top
C430  0.1u/10v_4  [CC0402]  158.84 55.1 180 top
C431  *10u/6.3v_6  [CC0603]  93.24 54.84 0 top
C432  *1u/6.3v_4  [CC0402]  124.99 54.84 180 top
C433  *1u/6.3v_4  [CC0402]  96.4 54.44 0 top
C434  1u/6.3v_4  [CC0402]  82.38 53.96 90 top
C435  *1u/6.3v_4  [CC0402]  83.52 53.96 90 top
C436  0.047u/25v_4  [CC0402]  84.67 53.96 90 top
C437  0.047u/25v_4  [CC0402]  74.43 53.91 90 top
C438  0.047u/25v_4  [CC0402]  62.24 53.83 0 top
C439  470p/50v_4  [CC0402]  64.47 53.83 0 top
C440  *1u/6.3v_4  [CC0402]  86.01 53.83 90 top
C441  *1u/6.3v_4  [CC0402]  87.23 53.83 90 top
C442  *1u/6.3v_4  [CC0402]  91.27 53.83 90 top
C443  *1u/6.3v_4  [CC0402]  102.45 53.83 90 top
C444  1u/6.3v_4  [CC0402]  103.84 53.83 90 top
C445  *1u/6.3v_4  [CC0402]  105.11 53.83 90 top
C446  *1u/6.3v_4  [CC0402]  108.67 53.83 90 top
C447  *0.1u/10v_4  [CC0402]  109.69 53.83 90 top
C448  *1u/6.3v_4  [CC0402]  117.69 53.83 90 top
C449  *1u/6.3v_4  [CC0402]  73.3 53.82 90 top
C450  1u/6.3v_4  [CC0402]  75.59 53.82 90 top
C451  *0.1u/10v_4  [CC0402]  78.76 53.82 90 top
C452  *1u/6.3v_4  [CC0402]  79.9 53.82 90 top
C453  *1u/6.3v_4  [CC0402]  80.92 53.82 90 top
C454  *1u/6.3v_4  [CC0402]  98.19 53.82 90 top
C455  *0.1u/10v_4  [CC0402]  99.72 53.82 90 top
C456  *1u/6.3v_4  [CC0402]  101.11 53.82 90 top
C457  *0.1u/10v_4  [CC0402]  112.92 53.82 90 top
C458  *0.1u/10v_4  [CC0402]  121.94 53.82 90 top
C459  *1u/6.3v_4  [CC0402]  88.6 53.81 90 top
C460  *0.1u/10v_4  [CC0402]  116.21 53.78 90 top
C461  *10u/6.3v_6  [CC0603]  120.46 53.58 270 top
C462  10u/6.3v_6  [CC0603]  106.45 53.57 270 top
C463  10u/6.3v_6  [CC0603]  111.78 53.57 270 top
C464  10u/6.3v_6  [CC0603]  118.89 53.57 270 top
C465  10u/6.3v_6  [CC0603]  89.87 53.3 270 top
C466  0.047u/25v_4  [CC0402]  113.62 51.93 0 top
C467  *1u/6.3v_4  [CC0402]  68.67 51.67 0 top
C468  kbl@4.7u/6.3v_6  [CC0603]  72.98 51.5 90 top
C469  10u/6.3v_6  [CC0603]  159.09 51.42 0 top
C470  kbl@0.01u/16v_4  [CC0402]  74.25 51.29 90 top
C471  10u/6.3v_6  [CC0603]  232.5 51.29 270 top
C472  0.1u/10v_4  [CC0402]  228.94 51.16 270 top
C473  0.1u/10v_4  [CC0402]  229.96 51.16 270 top
C474  *0.1u/10v_4  [CC0402]  85.68 49.77 90 top
C475  *0.1u/10v_4  [CC0402]  86.83 49.77 90 top
C476  *100p/50v_4  [CC0402]  65.49 49.39 0 top
C477  10u/6.3v_6  [CC0603]  230.59 49.13 180 top
C478  *0.1u/10v_4  [CC0402]  240.75 48.88 90 top
C479  10u/6.3v_6  [CC0603]  237.07 48.62 270 top
C480  *10u/6.3v_6  [CC0603]  239.61 48.62 270 top
C481  *100p/50v_4  [CC0402]  65.49 48.24 0 top
C482  10u/6.3v_6  [CC0603]  233.77 48.24 270 top
C483  *1000p/50v_4  [CC0402]  235.42 47.61 0 top
C484  10u/6.3v_6  [CC0603]  231.23 47.23 270 top
C485  kbl@2.2u/6.3v_6  [CC0603]  76.54 47.1 0 top
C486  10u/6.3v_6  [CC0603]  238.46 46.34 180 top
C487  0.1u/10v_4  [CC0402]  234.4 46.21 0 top
C488  0.1u/10v_4  [CC0402]  236.18 45.83 270 top
C489  0.1u/10v_4  [CC0402]  230.84 45.32 0 top
C490  2.2u/6.3v_6  [CC0603]  239.73 44.94 180 top
C491  0.1u/10v_4  [CC0402]  240.62 43.8 180 top
C492  *1000p/50v_4  [CC0402]  155.79 43.67 180 top
C493  *1000p/50v_4  [CC0402]  145.5 43.42 0 top
C494  10u/6.3v_6  [CC0603]  228.18 43.16 270 top
C495  0.1u/10v_4  [CC0402]  229.45 43.04 270 top
C496  2.2u/6.3v_6  [CC0603]  240.88 42.4 180 top
C497  10u/6.3v_6  [CC0603]  226.53 41.13 0 top
C498  22p/50v_4  [CC0402]  228.94 41.13 180 top
C499  10u/6.3v_6  [CC0603]  226.53 38.59 0 top
C500  0.1u/10v_4  [CC0402]  240.62 38.59 180 top
C501  2.2u/6.3v_6  [CC0603]  243.04 38.46 180 top
C502  0.1u/10v_4  [CC0402]  228.43 38.21 90 top
C503  *100p/50v_4  [CC0402]  229.57 38.21 90 top
C504  10u/6.3v_6  [CC0603]  241.26 37.19 180 top
C505  *10u/6.3v_6  [CC0603]  243.29 36.56 90 top
C506  0.1u/10v_4  [CC0402]  239.35 36.18 90 top
C507  10u/6.3v_6  [CC0603]  241.26 35.92 180 top
C508  1u/16v_6  [CC0603]  230.34 35.29 90 top
C509  100p/50v_4  [CC0402]  230.34 32.88 90 top
C510  2.2u/6.3v_6  [CC0603]  240.37 30.08 270 top
C511  2.2u/6.3v_6  [CC0603]  241.64 30.08 270 top
C512  22p/50v_4  [CC0402]  229.19 28.05 0 top
C513  22p/50v_4  [CC0402]  231.23 28.05 180 top
C514  *1000p/50v_4  [CC0402]  235.29 26.4 0 top
C515  10u/6.3v_6  [CC0603]  239.48 26.27 90 top
C516  1000p/50v_4  [CC0402]  234.02 16.49 0 top
C517  *68p/50v_4  [CC0402]  236.81 5.95 0 top
C518  *68p/50v_4  [CC0402]  240.12 5.95 180 top
C519  *68p/50v_4  [CC0402]  233.51 3.67 90 top
C520  *68p/50v_4  [CC0402]  235.04 3.67 90 top
C521  *6.8p/50v_4  [CC0402]  147.79 166.99 180 bottom
C522  *6.8p/50v_4  [CC0402]  147.79 165.59 180 bottom
C523  *0.1u/10v_4  [CC0402]  11.01 165.34 0 bottom
C524  ev@1u/6.3v_4  [CC0402]  61.12 165.19 0 bottom
C525  ev@0.1u/10v_4  [CC0402]  58.94 165.07 180 bottom
C526  ev@1u/6.3v_4  [CC0402]  38.87 164.43 90 bottom
C527  ev@1u/6.3v_4  [CC0402]  39.89 164.43 90 bottom
C528  220p/3kv_1808  [CC1808]  153.88 164.19 90 bottom
C529  *ev@120p/50v_4  [CC0402]  31 164.18 270 bottom
C530  ev@4.7u/6.3v_6  [CC0603]  33.54 163.8 270 bottom
C531  ev@1u/6.3v_4  [CC0402]  34.68 163.8 90 bottom
C532  ev@1u/6.3v_4  [CC0402]  35.7 163.8 90 bottom
C533  ev@1u/6.3v_4  [CC0402]  36.71 163.8 90 bottom
C534  ev@0.1u/10v_4  [CC0402]  37.73 163.8 90 bottom
C535  ev@1u/6.3v_4  [CC0402]  51.83 163.54 90 bottom
C536  *ev@120p/50v_4  [CC0402]  52.97 163.54 270 bottom
C537  ev@0.1u/10v_4  [CC0402]  54.11 163.54 270 bottom
C538  ev@0.1u/10v_4  [CC0402]  55.25 163.54 270 bottom
C539  ev@0.1u/10v_4  [CC0402]  56.4 163.54 270 bottom
C540  ev@10u/6.3v_6  [CC0603]  50.61 163.31 270 bottom
C541  ev@10u/6.3v_6  [CC0603]  57.54 163.16 270 bottom
C542  ev@4.7u/6.3v_6  [CC0603]  30.44 162.53 0 bottom
C543  *0.1u/10v_4  [CC0402]  110.96 161.65 0 bottom
C544  *10p/50v_4  [CC0402]  107.4 161.27 90 bottom
C545  ev@0.1u/10v_4  [CC0402]  31 161.26 0 bottom
C546  ev@4.7u/6.3v_6  [CC0603]  57.41 161.26 180 bottom
C547  *220p/50v_4  [CC0402]  110.96 160.64 0 bottom
C548  ev@0.1u/10v_4  [CC0402]  31 160.11 180 bottom
C549  *220p/50v_4  [CC0402]  83.78 159.37 0 bottom
C550  ev@0.1u/10v_4  [CC0402]  31 158.97 180 bottom
C551  0.1u/10v_4  [CC0402]  104.1 158.73 180 bottom
C552  *6.8p/50v_4  [CC0402]  152.61 158.35 0 bottom
C553  0.1u/10v_4  [CC0402]  72.86 158.23 270 bottom
C554  0.1u/10v_4  [CC0402]  74 158.23 270 bottom
C555  0.1u/10v_4  [CC0402]  75.27 158.23 270 bottom
C556  0.1u/10v_4  [CC0402]  76.41 158.23 270 bottom
C557  0.1u/10v_4  [CC0402]  77.68 158.23 270 bottom
C558  0.1u/10v_4  [CC0402]  78.83 158.23 270 bottom
C559  0.1u/10v_4  [CC0402]  80.22 158.23 270 bottom
C560  0.1u/10v_4  [CC0402]  81.37 158.23 270 bottom
C561  0.1u/10v_4  [CC0402]  107.27 157.97 90 bottom
C562  0.1u/10v_4  [CC0402]  104.1 157.72 180 bottom
C563  ev@0.1u/10v_4  [CC0402]  56.65 157.32 270 bottom
C564  0.1u/10v_4  [CC0402]  108.42 157.21 90 bottom
C565  0.1u/10v_4  [CC0402]  99.02 157.08 180 bottom
C566  *6.8p/50v_4  [CC0402]  152.61 156.96 0 bottom
C567  1u/6.3v_4  [CC0402]  99.02 156.07 0 bottom
C568  0.1u/10v_4  [CC0402]  109.94 155.69 0 bottom
C569  ev@0.01u/25v_4  [CC0402]  31 155.54 180 bottom
C570  0.1u/10v_4  [CC0402]  98 154.92 180 bottom
C571  ev@4.7u/6.3v_6  [CC0603]  72.73 154.67 90 bottom
C572  *470u/2v_7343  [CC7343]  126.32 154.67 90 bottom
C573  ev@1u/6.3v_4  [CC0402]  71.21 154.54 270 bottom
C574  0.1u/10v_4  [CC0402]  109.94 152.64 180 bottom
C575  0.1u/10v_4  [CC0402]  109.94 151.62 180 bottom
C576  ev@4.7u/6.3v_6  [CC0603]  76.46 150.08 270 bottom
C577  ev@0.1u/10v_4  [CC0402]  70.19 149.88 270 bottom
C578  ev@0.1u/10v_4  [CC0402]  71.46 149.88 90 bottom
C579  ev@0.1u/10v_4  [CC0402]  72.73 149.88 90 bottom
C580  ev@0.1u/10v_4  [CC0402]  74 149.88 270 bottom
C581  ev@0.1u/10v_4  [CC0402]  67.83 149.83 90 bottom
C582  ev@1u/6.3v_4  [CC0402]  68.97 149.83 90 bottom
C583  ev@0.1u/10v_4  [CC0402]  75.19 149.83 90 bottom
C584  *1000p/50v_4  [CC0402]  84.16 148.7 0 bottom
C585  4.7u/6.3v_6  [CC0603]  110.45 148.45 180 bottom
C586  *22u/6.3v_8  [CC0805]  125.05 148.45 0 bottom
C587  ev@0.1u/10v_4  [CC0402]  69.58 148.15 180 bottom
C588  0.1u/10v_4  [CC0402]  108.54 148.07 90 bottom
C589  10u/6.3v_6  [CC0603]  98.38 147.81 0 bottom
C590  *0.1u/10v_4  [CC0402]  84.16 147.56 0 bottom
C591  ev@4.7u/6.3v_6  [CC0603]  76.46 147.54 180 bottom
C592  ev@1u/6.3v_4  [CC0402]  74.56 147.16 90 bottom
C593  *10p/50v_4  [CC0402]  100.8 146.8 180 bottom
C594  *10p/50v_4  [CC0402]  102.83 146.8 0 bottom
C595  22u/6.3v_8  [CC0805]  124.67 146.41 0 bottom
C596  ev@1u/6.3v_4  [CC0402]  76.46 146.27 0 bottom
C597  0.1u/10v_4  [CC0402]  104.48 145.91 90 bottom
C598  0.1u/10v_4  [CC0402]  105.5 145.91 90 bottom
C599  0.1u/10v_4  [CC0402]  106.64 145.91 90 bottom
C600  0.1u/10v_4  [CC0402]  107.65 145.91 90 bottom
C601  *ev@120p/50v_4  [CC0402]  76.46 145.13 180 bottom
C602  22u/6.3v_8  [CC0805]  124.67 144.38 180 bottom
C603  ev@1u/6.3v_4  [CC0402]  76.46 143.98 0 bottom
C604  ev@10u/6.3v_6  [CC0603]  76.72 142.71 180 bottom
C605  *22u/6.3v_8  [CC0805]  119.85 142.6 270 bottom
C606  22u/6.3v_8  [CC0805]  121.88 142.6 90 bottom
C607  22u/6.3v_8  [CC0805]  124.67 142.35 180 bottom
C608  ev@10u/6.3v_6  [CC0603]  76.72 141.32 180 bottom
C609  ev@0.1u/10v_4  [CC0402]  76.34 140.05 0 bottom
C610  ev@1u/6.3v_4  [CC0402]  76.34 138.9 0 bottom
C611  ev@4.7u/6.3v_6  [CC0603]  28.28 138.29 270 bottom
C612  0.1u/10v_4  [CC0402]  123.15 137.78 270 bottom
C613  0.1u/10v_4  [CC0402]  124.16 137.78 270 bottom
C614  ev@0.22u/10v_4  [CC0402]  132.04 137.27 90 bottom
C615  ev@0.22u/10v_4  [CC0402]  133.05 137.27 90 bottom
C616  ev@0.22u/10v_4  [CC0402]  134.2 137.27 90 bottom
C617  ev@0.22u/10v_4  [CC0402]  135.21 137.27 90 bottom
C618  47u/6.3v_8  [CC0805]  137.75 136.89 180 bottom
C619  47u/6.3v_8  [CC0805]  141.18 136.89 0 bottom
C620  ev@1u/6.3v_4  [CC0402]  77.94 136.64 90 bottom
C621  *4.7u/6.3v_6  [CC0603]  106.16 136.25 180 bottom
C622  *0.1u/10v_4  [CC0402]  103.84 136.13 0 bottom
C623  0.1u/10v_4  [CC0402]  101.81 135.49 0 bottom
C624  0.1u/10v_4  [CC0402]  122.13 134.86 270 bottom
C625  0.1u/10v_4  [CC0402]  123.15 134.86 270 bottom
C626  0.1u/10v_4  [CC0402]  124.16 134.86 270 bottom
C627  0.1u/10v_4  [CC0402]  125.18 134.86 270 bottom
C628  ev@1u/6.3v_4  [CC0402]  77.1 134.2 270 bottom
C629  ev@0.1u/10v_4  [CC0402]  78.24 134.2 270 bottom
C630  12p/50v_4  [CC0402]  128.86 134.1 270 bottom
C631  12p/50v_4  [CC0402]  130.13 134.1 270 bottom
C632  ev@0.22u/10v_4  [CC0402]  131.28 134.1 90 bottom
C633  ev@0.22u/10v_4  [CC0402]  132.29 134.1 270 bottom
C634  1u/6.3v_4  [CC0402]  135.54 134.1 270 bottom
C635  1u/6.3v_4  [CC0402]  136.86 134.1 270 bottom
C636  1u/6.3v_4  [CC0402]  140.93 134.1 90 bottom
C637  ev@0.22u/10v_4  [CC0402]  133.5 134.09 90 bottom
C638  ev@0.22u/10v_4  [CC0402]  134.51 134.09 90 bottom
C639  ev@0.1u/10v_4  [CC0402]  76.72 132.17 0 bottom
C640  ev@4.7u/6.3v_6  [CC0603]  76.54 130.88 180 bottom
C641  ev@0.1u/10v_4  [CC0402]  76.21 129.63 0 bottom
C642  ev@0.1u/10v_4  [CC0402]  76.21 128.49 0 bottom
C643  ev@4.7u/6.3v_6  [CC0603]  74.76 127.19 180 bottom
C644  ev@10u/6.3v_6  [CC0603]  74.76 125.8 180 bottom
C645  ev@0.1u/10v_4  [CC0402]  74.51 124.53 0 bottom
C646  ev@0.1u/10v_4  [CC0402]  74.51 123.51 180 bottom
C647  ev@0.1u/10v_4  [CC0402]  60.72 122.52 90 bottom
C648  ev@0.1u/10v_4  [CC0402]  61.73 122.52 90 bottom
C649  ev@0.01u/25v_4  [CC0402]  67.7 122.52 270 bottom
C650  ev@0.1u/10v_4  [CC0402]  68.84 122.52 90 bottom
C651  ev@0.1u/10v_4  [CC0402]  70.11 122.52 90 bottom
C652  ev@0.1u/10v_4  [CC0402]  71.38 122.52 270 bottom
C653  ev@0.1u/10v_4  [CC0402]  72.65 122.52 270 bottom
C654  ev@4.7u/6.3v_6  [CC0603]  62.87 122.39 90 bottom
C655  *ev@120p/50v_4  [CC0402]  74.56 122.27 180 bottom
C656  ev@10p/50v_4  [CC0402]  58.76 120.89 90 bottom
C657  *1000p/50v_4  [CC0402]  157.06 119.24 90 bottom
C658  ev@10p/50v_4  [CC0402]  58.76 118.86 270 bottom
C659  *0.1u/10v_4  [CC0402]  158.07 117.71 0 bottom
C660  *1u/6.3v_4  [CC0402]  148.68 115.93 0 bottom
C661  *47u/6.3v_8  [CC0805]  154.9 114.79 180 bottom
C662  1u/6.3v_4  [CC0402]  46.69 107.91 270 bottom
C663  *2.2u/6.3v_6  [CC0603]  46.82 105.52 270 bottom
C664  15p/50v_4  [CC0402]  152.49 103.49 0 bottom
C665  15p/50v_4  [CC0402]  152.49 102.47 0 bottom
C666  0.1u/10v_4  [CC0402]  58 100.82 90 bottom
C667  0.1u/10v_4  [CC0402]  59.01 100.82 90 bottom
C668  0.1u/10v_4  [CC0402]  60.03 100.82 90 bottom
C669  0.1u/10v_4  [CC0402]  61.05 100.82 90 bottom
C670  0.1u/10v_4  [CC0402]  62.06 100.82 90 bottom
C671  0.1u/10v_4  [CC0402]  63.08 100.82 90 bottom
C672  0.1u/10v_4  [CC0402]  64.09 100.82 90 bottom
C673  0.1u/10v_4  [CC0402]  65.11 100.82 90 bottom
C674  0.1u/10v_4  [CC0402]  56.73 100.69 90 bottom
C675  0.01u/16v_4  [CC0402]  51.46 100.69 90 bottom
C676  0.1u/10v_4  [CC0402]  52.6 100.69 270 bottom
C677  *0.1u/10v_4  [CC0402]  155.91 100.57 0 bottom
C678  *10p/50v_4  [CC0402]  141.18 99.81 0 bottom
C679  *10p/50v_4  [CC0402]  143.47 99.81 180 bottom
C680  0.1u/10v_4  [CC0402]  66.76 98.41 90 bottom
C681  0.1u/10v_4  [CC0402]  67.78 98.41 90 bottom
C682  1u/6.3v_4  [CC0402]  150.58 97.65 90 bottom
C683  0.1u/10v_4  [CC0402]  151.6 97.65 270 bottom
C684  0.01u/16v_4  [CC0402]  32.22 94.73 270 bottom
C685  0.01u/16v_4  [CC0402]  33.23 94.73 270 bottom
C686  0.01u/16v_4  [CC0402]  34.25 94.73 270 bottom
C687  0.01u/16v_4  [CC0402]  35.26 94.73 270 bottom
C688  *1000p/50v_4  [CC0402]  216.62 93.58 90 bottom
C689  *0.1u/10v_4  [CC0402]  217.64 93.58 90 bottom
C690  *0.1u/10v_4  [CC0402]  218.65 93.58 90 bottom
C691  100u/6.3v_1206  [CC1206]  232.11 87.49 270 bottom
C692  1000p/50v_4  [CC0402]  233.89 87.49 270 bottom
C693  1u/6.3v_4  [CC0402]  232.5 76.31 180 bottom
C694  1u/6.3v_4  [CC0402]  72.22 73.77 270 bottom
C695  *1u/6.3v_4  [CC0402]  73.43 73.76 270 bottom
C696  *0.1u/10v_4  [CC0402]  74.57 73.76 270 bottom
C697  *0.1u/10v_4  [CC0402]  76.6 73.76 270 bottom
C698  1u/6.3v_4  [CC0402]  88.67 73.25 180 bottom
C699  *0.1u/10v_4  [CC0402]  217.38 72.88 180 bottom
C700  *0.1u/10v_4  [CC0402]  64.54 72.41 0 bottom
C701  0.1u/10v_4  [CC0402]  217.38 71.74 180 bottom
C702  *0.1u/10v_4  [CC0402]  64.54 71.35 0 bottom
C703  *0.1u/10v_4  [CC0402]  64.54 70.21 0 bottom
C704  *1u/6.3v_4  [CC0402]  124.98 69.83 180 bottom
C705  *10u/6.3v_6  [CC0603]  64.09 69.07 180 bottom
C706  100u/6.3v_1206  [CC1206]  232.11 68.94 270 bottom
C707  1000p/50v_4  [CC0402]  233.89 68.94 270 bottom
C708  *1u/6.3v_4  [CC0402]  124.99 68.55 180 bottom
C709  *0.1u/10v_4  [CC0402]  64.47 67.8 0 bottom
C710  1u/6.3v_4  [CC0402]  130.77 65.39 270 top
C711  1u/6.3v_4  [CC0402]  127.9 65.59 0 top
C712  *1u/6.3v_4  [CC0402]  124.99 67.03 180 bottom
C713  1u/6.3v_4  [CC0402]  64.47 66.66 0 bottom
C714  10u/6.3v_6  [CC0603]  219.54 65.64 90 bottom
C715  1u/6.3v_4  [CC0402]  124.99 65.38 180 bottom
C716  1u/6.3v_4  [CC0402]  127.49 64.07 270 top
C717  1u/6.3v_4  [CC0402]  224.49 62.85 180 bottom
C718  *0.1u/10v_4  [CC0402]  124.99 62.33 180 bottom
C719  *0.1u/10v_4  [CC0402]  124.99 60.81 180 bottom
C720  *0.1u/10v_4  [CC0402]  124.99 59.28 180 bottom
C721  gs@22p/50v_4  [CC0402]  214.72 59.67 270 bottom
C722  gs@10u/6.3v_6  [CC0603]  217.38 58.66 180 bottom
C723  *1u/6.3v_4  [CC0402]  124.99 57.38 180 bottom
C724  gs@0.1u/10v_4  [CC0402]  220.3 56.5 180 bottom
C725  1u/6.3v_4  [CC0402]  60.41 56.37 270 bottom
C726  1u/6.3v_4  [CC0402]  64.47 56.12 180 bottom
C727  1u/6.3v_4  [CC0402]  124.99 55.85 180 bottom
C728  1u/6.3v_4  [CC0402]  93.11 55.47 180 bottom
C729  1u/6.3v_4  [CC0402]  61.81 54.47 90 bottom
C730  1u/6.3v_4  [CC0402]  62.95 54.47 90 bottom
C731  1u/6.3v_4  [CC0402]  64.09 54.47 90 bottom
C732  1u/6.3v_4  [CC0402]  67.58 54.33 180 bottom
C733  *1u/6.3v_4  [CC0402]  77.74 54.33 180 bottom
C734  *1u/6.3v_4  [CC0402]  93.11 54.33 180 bottom
C735  *0.1u/10v_4  [CC0402]  96.41 54.18 0 bottom
C736  *0.1u/10v_4  [CC0402]  65.87 53.96 90 bottom
C737  *10u/6.3v_6  [CC0603]  70.06 53.96 0 bottom
C738  *0.1u/10v_4  [CC0402]  82.25 53.83 90 bottom
C739  *0.1u/10v_4  [CC0402]  99.7 53.83 90 bottom
C740  1u/6.3v_4  [CC0402]  102.47 53.83 90 bottom
C741  0.047u/25v_4  [CC0402]  105.62 53.83 90 bottom
C742  1u/6.3v_4  [CC0402]  113.88 53.83 90 bottom
C743  *1u/6.3v_4  [CC0402]  120.3 53.83 90 bottom
C744  *0.1u/10v_4  [CC0402]  83.46 53.82 90 bottom
C745  1u/6.3v_4  [CC0402]  84.73 53.82 90 bottom
C746  *0.1u/10v_4  [CC0402]  86 53.82 90 bottom
C747  *1u/6.3v_4  [CC0402]  87.27 53.82 90 bottom
C748  *1u/6.3v_4  [CC0402]  91.21 53.82 90 bottom
C749  1u/6.3v_4  [CC0402]  101.11 53.82 90 bottom
C750  *1u/6.3v_4  [CC0402]  106.83 53.82 90 bottom
C751  *1u/6.3v_4  [CC0402]  108.73 53.82 90 bottom
C752  *1u/6.3v_4  [CC0402]  119.27 53.82 90 bottom
C753  *1u/6.3v_4  [CC0402]  121.33 53.82 90 bottom
C754  *0.1u/10v_4  [CC0402]  88.54 53.8 90 bottom
C755  *0.1u/10v_4  [CC0402]  89.94 53.8 90 bottom
C756  10u/6.3v_6  [CC0603]  75.71 53.57 270 bottom
C757  gs@33p/50v_4  [CC0402]  220.3 53.32 0 bottom
C758  0.047u/25v_4  [CC0402]  77.71 53.3 0 bottom
C759  0.047u/25v_4  [CC0402]  80.22 53.2 180 bottom
C760  10u/6.3v_6  [CC0603]  72.22 52.56 0 bottom
C761  0.1u/10v_4  [CC0402]  89.49 51.93 0 bottom
C762  0.047u/25v_4  [CC0402]  110.93 51.93 0 bottom
C763  gs@33p/50v_4  [CC0402]  219.41 51.67 270 bottom
C764  *0.1u/10v_4  [CC0402]  64.86 51.67 0 bottom
C765  0.047u/25v_4  [CC0402]  112.48 51.42 270 bottom
C766  0.1u/10v_4  [CC0402]  81.49 51.29 0 bottom
C767  0.1u/10v_4  [CC0402]  147.28 51.16 90 bottom
C768  *0.1u/10v_4  [CC0402]  110.14 48.62 0 bottom
C769  0.1u/10v_4  [CC0402]  106.51 46.34 0 bottom
C770  tpm@0.1u/10v_4  [CC0402]  172.3 46.08 180 bottom
C771  0.1u/10v_4  [CC0402]  224.49 45.7 270 bottom
C772  tpm@10u/6.3v_4  [CC0402]  160.36 45.58 180 bottom
C773  10u/6.3v_6  [CC0603]  222.08 45.45 270 bottom
C774  *4.7u/6.3v_6  [CC0603]  223.35 45.45 270 bottom
C775  tpmn@10u/6.3v_4  [CC0402]  172.3 45.07 0 bottom
C776  tpm@0.1u/10v_4  [CC0402]  160.36 44.56 0 bottom
C777  10p/50v_4  [CC0402]  224.49 43.04 90 bottom
C778  tpm@0.1u/10v_4  [CC0402]  160.36 42.15 0 bottom
C779  10p/50v_4  [CC0402]  224.49 40.5 270 bottom
C781  0.1u/10v_4  [CC0402]  234.02 15.22 180 top
CN1  rj45  [RJ45-JM361C-HP34AA03-9H-8P]  133.53 171.21 0 bottom
CN2  aba-hdm-022-p05  [HDMI-C12826-11905-L-19P-SMT]  80.71 170.25 0 bottom
CN3  crt conn  [DSUB-10296-00021-15P]  108.7 167.96 0 bottom
CN4  ev@fan2  [50224-00401-001-4P-L]  18.17 157.96 270 bottom
CN5  usb2.0 conn  [UB2-C14793-10409-L-4P-R]  246.53 145.14 270 bottom
CN6  usb/b conn  [50501-0120N-001-12P-L]  5.95 115.68 90 bottom
CN7  50398-04071-001  [GS12401-1011-9H-40P-R]  62.3 106.7 0 bottom
CN8  usb3.0 conn  [UB3-50928-0090A-001-9P]  247.13 90.91 270 bottom
CN9  bat_conn  [BAT-23_2-4_2]  81.24 90.15 270 bottom
CN10  fan1  [50224-00401-001-4P-L]  185.87 86.63 0 bottom
CN11  sata_hdd  [SATA-51205-0134T-001-13P-R]  33.06 82.21 90 bottom
CN12  wlan_ngff conn(type 2230)_51745-0750p-005  [NGFF-APCI0076-P001A-75P-KE]  222.46 81.96 90 bottom
CN13  usb3.0 conn  [UB3-50928-0090A-001-9P]  247.13 72.91 270 bottom
CN14  *aces_88511-180n  [88511-180N-18P-L]  148.03 57.58 180 bottom
CN15  kb_conn  [51596-02601-001-26P-L]  49.08 47.71 180 bottom
CN16  kbl@kb_backlight  [50503-0040N-V01-4P-L]  68.35 47.81 180 bottom
CN17  fingerprint/b  [196479-06041-3-6P-L]  77.2 47.54 180 bottom
CN18  tp cn  [88502-06XX-6P-L-SMT]  87.85 46.61 180 bottom
CN19  sd-card  [CARD-CS1R-111-H-N-11P]  236.63 45.96 270 bottom
CN20  amic  [50224-00401-001-4P-L]  234.78 16.97 90 bottom
CN21  sit_2sj3052-005111f  [PHJK-2SJ3052-005111F-7P]  245.78 15.76 270 bottom
CN22  spk cn  [50281-0040N-001-4P-L]  233.42 6.96 90 bottom
CP1  *100p/50vx4  [8P4R]  36.79 49.39 270 top
CP2  *100p/50vx4  [8P4R]  47.46 45.96 0 top
CP3  *100p/50vx4  [8P4R]  50.89 45.96 0 top
CP4  *100p/50vx4  [8P4R]  54.31 45.96 0 top
CP5  *100p/50vx4  [8P4R]  58 45.96 0 top
CP6  *100p/50vx4  [8P4R]  35.77 45.83 270 top
D1  *b88069x9231t203  [CC1812]  154.26 164.19 90 top
D2  rb500v-40  [DSM]  88.99 151.24 270 top
D3  *5v/0.2p_4  [CC0402]  236.18 146.92 270 top
D4  *5v/0.2p_4  [CC0402]  236.18 144.89 90 top
D5  rb500v-40  [DSM]  60.03 104.12 0 top
D6  *5v/0.2p_4  [CC0402]  233.89 94.09 270 top
D7  *5v/0.2p_4  [CC0402]  233.89 92.06 90 top
D8  *5v/0.2p_4  [CC0402]  233.89 89.52 270 top
D9  *5v/0.2p_4  [CC0402]  233.89 87.49 90 top
D10  *5v/0.2p_4  [CC0402]  233.89 76.18 270 top
D11  *5v/0.2p_4  [CC0402]  233.89 74.15 90 top
D12  *5v/0.2p_4  [CC0402]  233.89 71.61 270 top
D13  *5v/0.2p_4  [CC0402]  233.89 69.58 90 top
D14  *rb500v-40  [DSM]  161.12 60.44 90 top
D15  bat54c  [SOT23_213-3_3-2]  129.37 59.42 90 top
D16  sdmk0340l-7-f  [DSMV]  134.91 58.45 90 top
D17  rb500v-40  [DSM]  226.78 48.62 0 top
D18  rb500v-40  [DSM]  226.78 46.72 0 top
D19  rb500v-40  [DSM]  222.34 40.5 180 top
D20  rb500v-40  [DSM]  222.34 38.72 180 top
D21  *14v/100p_4  [CC0402]  229.19 27.03 0 top
D22  *14v/100p_4  [CC0402]  231.23 27.03 180 top
D23  *14v/100p_4  [CC0402]  236.81 24.37 0 top
D24  *14v/100p_4  [CC0402]  238.97 24.37 180 top
D25  *14v/100p_4  [CC0402]  241.26 24.11 0 top
D26  *14v/100p_4  [CC0402]  241.77 7.48 0 top
D27  *14v/100p_4  [CC0402]  83.78 160.38 180 bottom
D28  rb500v-40  [DSM]  88.99 151.24 270 bottom
D29  *5v/0.2p_4  [CC0402]  233.89 92.44 270 bottom
D30  *5v/0.2p_4  [CC0402]  233.89 90.41 90 bottom
D31  *5v/0.2p_4  [CC0402]  233.89 73.9 270 bottom
D32  *5v/0.2p_4  [CC0402]  233.89 71.87 90 bottom
D33  gs@rb500v-40  [DSM]  213.32 58.66 270 bottom
D34  rb500v-40  [DSM]  156.8 47.74 0 bottom
D35  *14v/100p_4  [CC0402]  106.51 47.48 0 bottom
D36  *rb500v-40  [DSM]  156.8 45.83 0 bottom
D37  rb500v-40  [DSM]  156.8 43.93 0 bottom
D38  rb500v-40  [DSM]  156.8 42.02 0 bottom
HOLE1  *h-c150d150n  [H-C150D150N]  120.35 149.41 0 top
HOLE2  *h-c150d150n  [H-C150D150N]  89.85 110.11 0 top
HOLE3  *h-c150d150n  [H-C150D150N]  150.85 110.11 0 top
HOLE4  *h-c236d157p2  [H-C236D157P2]  27.4 40.56 0 top
HOLE5  *hg-zrq-1  [HG-ZRQ-1]  181.2 38.56 0 top
HOLE6  *hg-c276d118p2  [HG-C276D118P2]  246.88 4.96 0 top
